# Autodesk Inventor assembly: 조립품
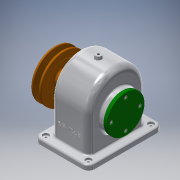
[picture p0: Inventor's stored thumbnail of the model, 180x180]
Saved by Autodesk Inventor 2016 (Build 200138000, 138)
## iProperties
Created: 2018-11
Part Number: 조립품
Material: 일반
Document SubType Name: Assembly
Designer: user
Author: user
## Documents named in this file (14)
- C:\Users\user\Desktop\481111V1012\조립품.iam
- C:\Users\user\Desktop\481111V1012\볼트 M4.ipt
- C:\Users\user\Desktop\481111V1012\부시.ipt
- C:\Users\user\Desktop\481111V1012\스퍼기어.ipt
- C:\Users\user\Desktop\481111V1012\앞커버.ipt
- C:\Users\user\Desktop\481111V1012\오일 실 28 40 8.ipt
- C:\Users\user\Desktop\481111V1012\축.ipt
- C:\Users\user\Desktop\481111V1012\키 5x5x18.ipt
- C:\Users\user\Desktop\481111V1012\키 6x6x22.ipt
- C:\Users\user\Desktop\481111V1012\V-벨트풀리.ipt
- C:\Users\user\Desktop\481111V1012\뒤커버.ipt
- C:\Users\user\Desktop\481111V1012\멈춤나사 M4.ipt
- C:\Users\user\Desktop\481111V1012\베어링 6203.ipt
- C:\Users\user\Desktop\481111V1012\본체.ipt
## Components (1 placed, 1 different names)
1. V-벨트풀리:1
